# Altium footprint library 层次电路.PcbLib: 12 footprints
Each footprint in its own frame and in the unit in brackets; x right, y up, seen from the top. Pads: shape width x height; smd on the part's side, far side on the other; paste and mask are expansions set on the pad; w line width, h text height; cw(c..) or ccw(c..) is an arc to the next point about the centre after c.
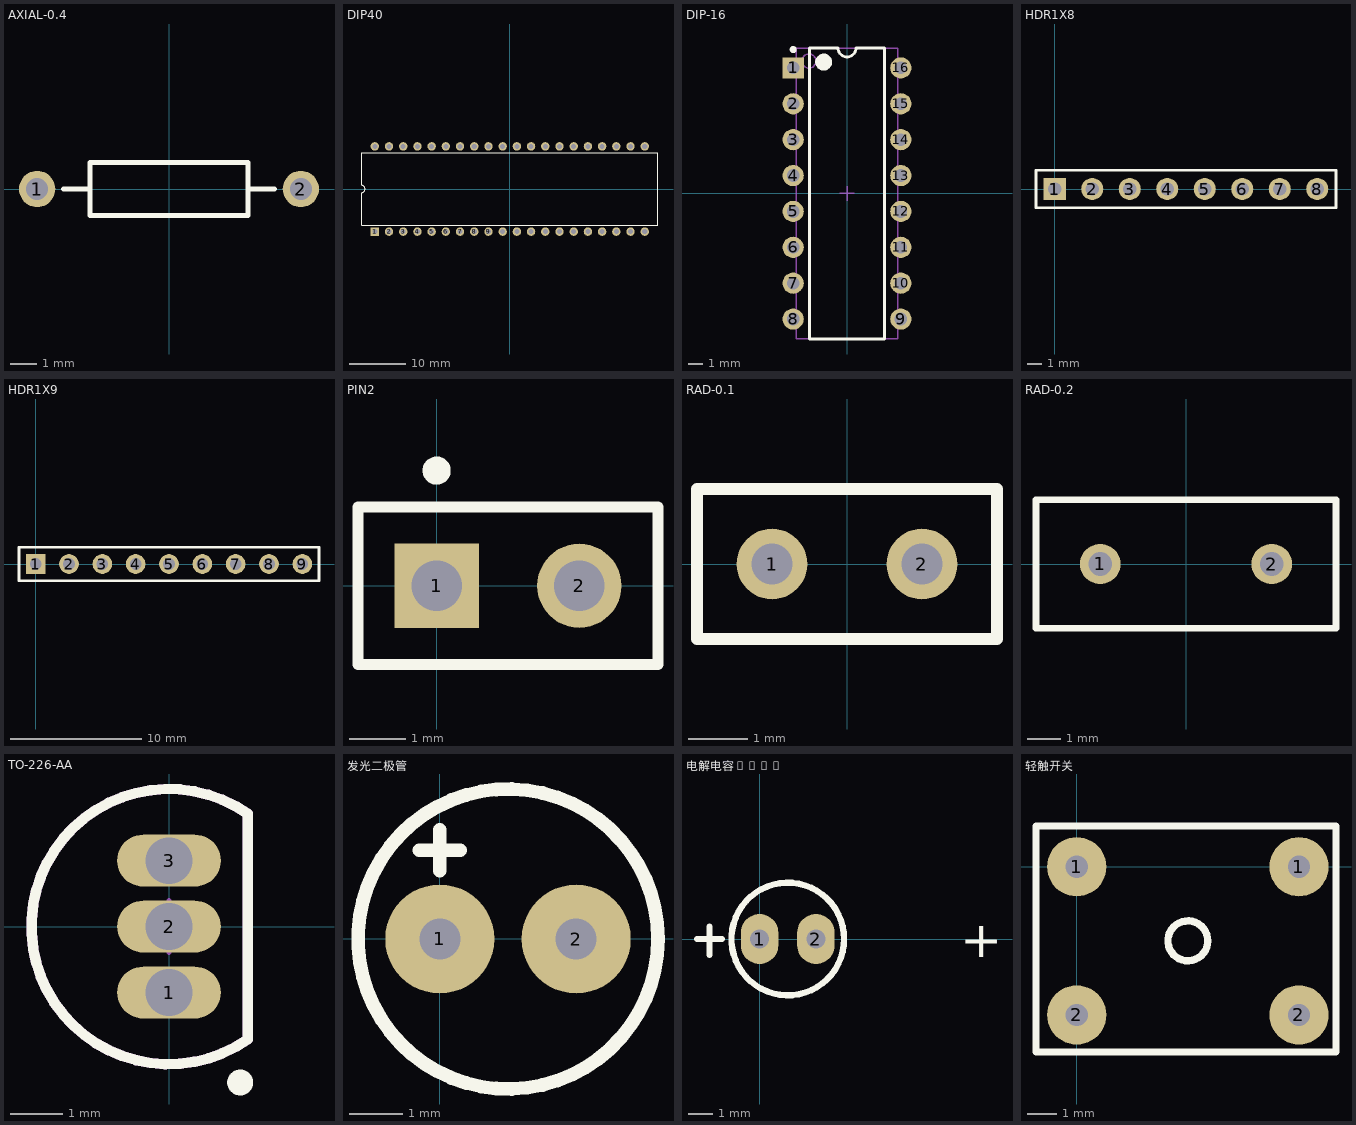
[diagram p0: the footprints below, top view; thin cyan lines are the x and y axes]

## AXIAL-0.4 [mm] "Axial Device, Thru-Hole; 2 Leads; 0.4 in Pin Spacing"
height 2.032
pads (2):
  round 1.4 hole 0.85: 1(-5.08,0) 2(5.08,0)
Top Overlay:
  lines w0.2: -4.064,0 -3.048,0 ; 3.048,0 4.064,0 ; -3.048,-1.016 -3.048,1.016 3.048,1.016 3.048,-1.016 -3.048,-1.016

## DIP40 [mm] "DIP; 40 Leads; Row Spacing 15.24 mm; Pitch 2.54 mm"
height 4.92
pads (40):
  rect 1.5x1.5 hole 0.9: 1(-24.13,-7.62)
  round 1.5 hole 0.9: 2(-21.59,-7.62) 3(-19.05,-7.62) 4(-16.51,-7.62) 5(-13.97,-7.62) 6(-11.43,-7.62) 7(-8.89,-7.62) 8(-6.35,-7.62) 9(-3.81,-7.62) 10(-1.27,-7.62) 11(1.27,-7.62) 12(3.81,-7.62) 13(6.35,-7.62) 14(8.89,-7.62) 15(11.43,-7.62) 16(13.97,-7.62) 17(16.51,-7.62) 18(19.05,-7.62) 19(21.59,-7.62) 20(24.13,-7.62) 21(24.13,7.62) 22(21.59,7.62) 23(19.05,7.62) 24(16.51,7.62) 25(13.97,7.62) 26(11.43,7.62) 27(8.89,7.62) 28(6.35,7.62) 29(3.81,7.62) 30(1.27,7.62) 31(-1.27,7.62) 32(-3.81,7.62) 33(-6.35,7.62) 34(-8.89,7.62) 35(-11.43,7.62) 36(-13.97,7.62) 37(-16.51,7.62) 38(-19.05,7.62) 39(-21.59,7.62) 40(-24.13,7.62)
Top Overlay:
  lines w0.2: -26.5,-6.45 -26.5,-0.635 ccw(c-26.5,0) -26.5,0.635 -26.5,6.45 26.5,6.45 26.5,-6.45 -26.5,-6.45

## DIP-16 [mm] "DIP; 16 Leads; Row Spacing 7.62 mm; Pitch 2.54 mm"
height 5.08
pads (16):
  rect 1.5x1.5 hole 0.9: 1(-3.81,8.89)
  round 1.5 hole 0.9: 2(-3.81,6.35) 3(-3.81,3.81) 4(-3.81,1.27) 5(-3.81,-1.27) 6(-3.81,-3.81) 7(-3.81,-6.35) 8(-3.81,-8.89) 9(3.81,-8.89) 10(3.81,-6.35) 11(3.81,-3.81) 12(3.81,-1.27) 13(3.81,1.27) 14(3.81,3.81) 15(3.81,6.35) 16(3.81,8.89)
Top Overlay:
  circle w0.25: c-3.81,10.19 r0.125
  circle w0.6: c-1.65,9.3 r0.3
  lines w0.2: -2.65,-10.3 -2.65,10.3 -0.635,10.3 ccw(c0,10.3) 0.635,10.3 2.65,10.3 2.65,-10.3 -2.65,-10.3
Mechanical 13:
  circle w0.1: c-2.7,9.375 r0.5
  lines w0.1: -3.6,-10.275 -3.6,10.275 3.6,10.275 3.6,-10.275 -3.6,-10.275
Mechanical 15:
  lines w0.1: -0.5,0 0.5,0 ; 0,-0.5 0,0.5
3D body: height 5.08, standoff 0, extent -3.6,-10.275 3.6,10.275

## HDR1X8 [mm] "Connector; Header; 8 Position"
height 0.9
pads (8):
  rect 1.5x1.5 hole 0.9: 1(0,0)
  round 1.5 hole 0.9: 2(2.54,0) 3(5.08,0) 4(7.62,0) 5(10.16,0) 6(12.7,0) 7(15.24,0) 8(17.78,0)
Top Overlay:
  lines w0.2: -1.27,-1.27 -1.27,1.27 19.05,1.27 19.05,-1.27 -1.27,-1.27

## HDR1X9 [mm] "Connector; Header; 9 Position"
height 0.9
pads (9):
  rect 1.5x1.5 hole 0.9: 1(0,0)
  round 1.5 hole 0.9: 2(2.54,0) 3(5.08,0) 4(7.62,0) 5(10.16,0) 6(12.7,0) 7(15.24,0) 8(17.78,0) 9(20.32,0)
Top Overlay:
  lines w0.2: -1.27,-1.27 -1.27,1.27 21.59,1.27 21.59,-1.27 -1.27,-1.27

## PIN2 [mm] "Photosensitive Diode; 2 Leads"
height 0.9
pads (2):
  rect 1.5x1.5 hole 0.9: 1(0,0)
  round 1.5 hole 0.9: 2(2.54,0)
Top Overlay:
  circle w0.25: c0,2.05 r0.125
  lines w0.2: -1.4,-1.4 -1.4,1.4 3.94,1.4 3.94,-1.4 -1.4,-1.4

## RAD-0.1 [mm] "Radial Cap, Thru-Hole; 2 Leads; 0.1 in Pin Spacing"
pads (2):
  round 1.2 hole 0.7: 1(-1.27,0) 2(1.27,0)
Top Overlay:
  lines w0.2: -2.54,-1.27 -2.54,1.27 2.54,1.27 2.54,-1.27 -2.54,-1.27

## RAD-0.2 [mm] "Radial Cap, Thru-Hole; 2 Leads; 0.2 in Pin Spacing"
pads (2):
  round 1.2 hole 0.7: 1(-2.54,0) 2(2.54,0)
Top Overlay:
  lines w0.2: -4.445,-1.905 4.445,-1.905 4.445,1.905 -4.445,1.905 -4.445,-1.905

## TO-226-AA [mm] "TO, Flat Index; 3 In-Line, Axial Leads; Body Dia. 4.8mm; Leads 0.55 x 0.51 mm (max)"
height 5.33
pads (3):
  oval 2x1 hole 0.9: 1(0,-1.27) 2(0,0) 3(0,1.27)
Top Overlay:
  circle w0.25: c1.371,-3.003 r0.125
  lines w0.2: 1.52,-2.171 cw(c0,0) 1.52,2.171 1.52,-2.171
Mechanical 13:
  lines w0.2: 1.52,-2.171 cw(c0,0) 1.52,2.171 1.52,-2.171
Mechanical 15:
  lines w0.1: -0.5,0 0.5,0 ; 0,-0.5 0,0.5
3D body: height 5.33, standoff 0, extent -2.651,-2.661 1.52,2.661

## 发光二极管 [mil]
height 35.43
pads (2):
  round 80 hole 30: 1(0,0) 2(100,0)
Top Overlay:
  circle w10: c50,0 r110
  lines w10: -15,65 15,65 ; 0,50 0,80

## 电解电容47UF [mil]
height 35.43
pads (2):
  oval 60x80 hole 30: 1(0,0) 2(90,0)
Top Overlay:
  circle w10: c45,0 r90
  lines w10: -100,0 -60,0 ; -80,-25 -80,20
  text "+" at 320.15,-29.01 h59.06

## 轻触开关 [mil]
height 35.43
pads (4):
  round 80 hole 30: 1(0,0) 1(300,0) 2(0,-200) 2(300,-200)
Top Overlay:
  circle w10: c150,-100 r26.93
  lines w10: -55,-250 350,-250 350,55 -55,55 -55,-250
